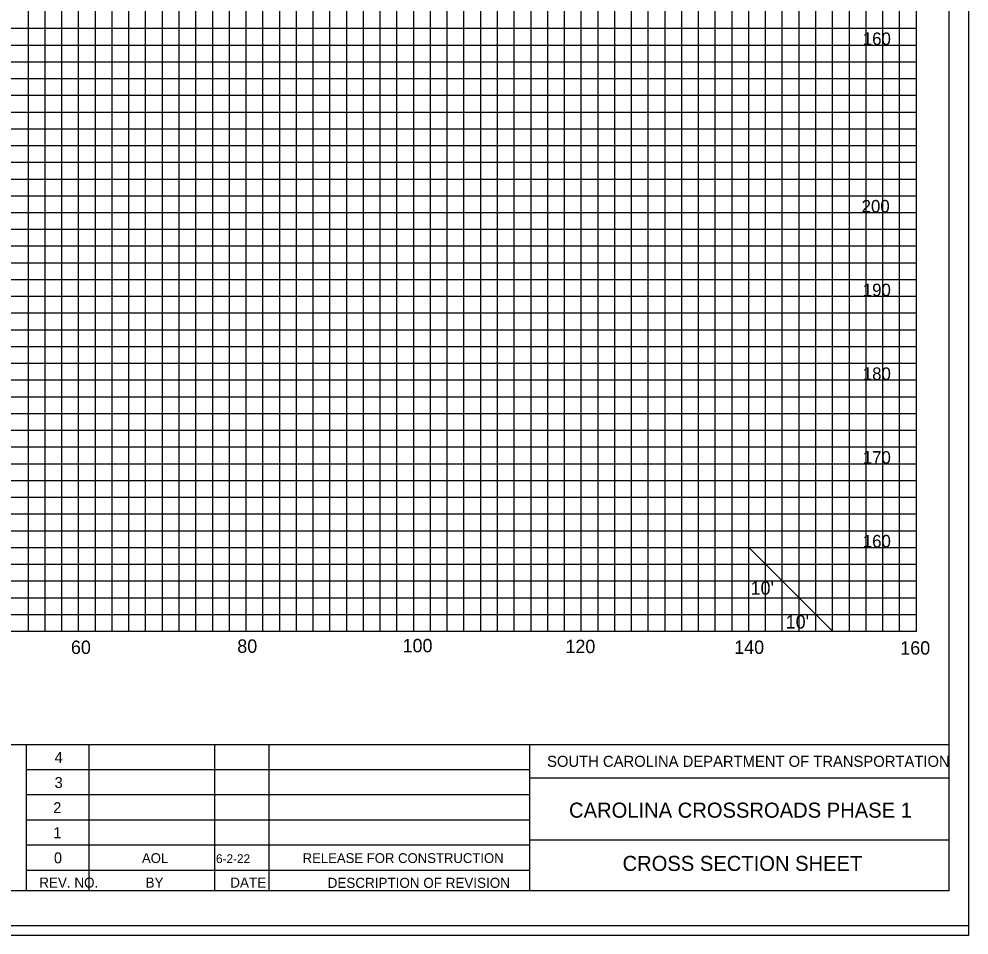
# Model space of a CAD drawing. Extents: x 967 to 1326, y 964 to 1184.
# Drawn here: x 1212.9 to 1326.3, y 963.7 to 1073.1 of the extents above; entities that cross this region are included whole.
import ezdxf

# ---------------------------------------------------------------- set-up
doc = ezdxf.new("R2010")
doc.units = 0
for name, color, linetype in [('Default', 7, 'Continuous'), ('RD_SHT_Bndy', 7, 'Continuous'), ('RD_SHT_IplotShp', 7, 'Continuous'), ('RD_SHT_Misc1', 7, 'Continuous'), ('RD_SHT_MjGrid', 7, 'Continuous'), ('RD_SHT_MnGrid', 7, 'Continuous'), ('RD_SHT_TX', 7, 'Continuous'), ('RD_Sketch1', 7, 'Continuous')]:
    doc.layers.add(name, color=color, linetype=linetype)

msp = doc.modelspace()

# ---------------------------------------------------------------- linework, layer by layer
at = {"layer": 'RD_SHT_Bndy'}
for p, q in [((1323.89, 1178.46), (1323.89, 968.98)), ((996.11, 986.49), (1323.89, 986.49)), ((1213.76, 968.94), (1213.76, 986.49)), ((1221.26, 968.95), (1221.26, 986.48)), ((1236.26, 968.95), (1236.26, 986.48)), ((1242.76, 968.95), (1242.76, 986.48)), ((1273.88, 968.98), (1273.88, 986.49)), ((1213.76, 983.48), (1273.88, 983.48)), ((1323.93, 982.43), (1273.88, 982.43)), ((1213.76, 980.48), (1273.88, 980.48)), ((1213.76, 977.48), (1273.88, 977.48)), ((1213.76, 974.48), (1273.88, 974.48)), ((1323.89, 975.04), (1273.88, 975.04)), ((1213.76, 971.48), (1273.88, 971.48)), ((1323.89, 968.98), (996.11, 968.98))]:
    msp.add_line(p, q, dxfattribs=at)
at = {"layer": 'RD_SHT_IplotShp'}
for points in [[(967.41, 963.72), (1326.28, 963.72), (1326.28, 1183.72), (967.41, 1183.72)], [(988.52, 964.84), (1326.28, 964.84), (1326.28, 1182.6), (988.52, 1182.6)]]:
    msp.add_lwpolyline(points, close=True, dxfattribs=at)
at = {"layer": 'RD_SHT_MjGrid'}
for p, q in [((1220, 1000), (1220, 1170)), ((1230, 1000), (1230, 1170)), ((1240, 1000), (1240, 1170)), ((1250, 1000), (1250, 1170)), ((1260, 1000), (1260, 1170)), ((1270, 1000), (1270, 1170)), ((1280, 1000), (1280, 1170)), ((1290, 1000), (1290, 1170)), ((1300, 1000), (1300, 1170)), ((1310, 1000), (1310, 1170)), ((1320, 1000), (1320, 1170)), ((1000, 1070), (1320, 1070)), ((1000, 1060), (1320, 1060)), ((1000, 1050), (1320, 1050)), ((1000, 1040), (1320, 1040)), ((1000, 1030), (1320, 1030)), ((1000, 1020), (1320, 1020)), ((1000, 1010), (1320, 1010)), ((1000, 1000), (1320, 1000))]:
    msp.add_line(p, q, dxfattribs=at)
at = {"layer": 'RD_SHT_MnGrid'}
for p, q in [((1214, 1000), (1214, 1170)), ((1216, 1000), (1216, 1170)), ((1218, 1000), (1218, 1170)), ((1222, 1000), (1222, 1170)), ((1224, 1000), (1224, 1170)), ((1226, 1000), (1226, 1170)), ((1228, 1000), (1228, 1170)), ((1232, 1000), (1232, 1170)), ((1234, 1000), (1234, 1170)), ((1236, 1000), (1236, 1170)), ((1238, 1000), (1238, 1170)), ((1242, 1000), (1242, 1170)), ((1244, 1000), (1244, 1170)), ((1246, 1000), (1246, 1170)), ((1248, 1000), (1248, 1170)), ((1252, 1000), (1252, 1170)), ((1254, 1000), (1254, 1170)), ((1256, 1000), (1256, 1170)), ((1258, 1000), (1258, 1170)), ((1262, 1000), (1262, 1170)), ((1264, 1000), (1264, 1170)), ((1266, 1000), (1266, 1170)), ((1268, 1000), (1268, 1170)), ((1272, 1000), (1272, 1170)), ((1274, 1000), (1274, 1170)), ((1276, 1000), (1276, 1170)), ((1278, 1000), (1278, 1170)), ((1282, 1000), (1282, 1170)), ((1284, 1000), (1284, 1170)), ((1286, 1000), (1286, 1170)), ((1288, 1000), (1288, 1170)), ((1292, 1000), (1292, 1170)), ((1294, 1000), (1294, 1170)), ((1296, 1000), (1296, 1170)), ((1298, 1000), (1298, 1170)), ((1302, 1000), (1302, 1170)), ((1304, 1000), (1304, 1170)), ((1306, 1000), (1306, 1170)), ((1308, 1000), (1308, 1170)), ((1312, 1000), (1312, 1170)), ((1314, 1000), (1314, 1170)), ((1316, 1000), (1316, 1170)), ((1318, 1000), (1318, 1170)), ((1000, 1072), (1320, 1072)), ((1000, 1068), (1320, 1068)), ((1000, 1066), (1320, 1066)), ((1000, 1064), (1320, 1064)), ((1000, 1062), (1320, 1062)), ((1000, 1058), (1320, 1058)), ((1000, 1056), (1320, 1056)), ((1000, 1054), (1320, 1054)), ((1000, 1052), (1320, 1052)), ((1000, 1048), (1320, 1048)), ((1000, 1046), (1320, 1046)), ((1000, 1044), (1320, 1044)), ((1000, 1042), (1320, 1042)), ((1000, 1038), (1320, 1038)), ((1000, 1036), (1320, 1036)), ((1000, 1034), (1320, 1034)), ((1000, 1032), (1320, 1032)), ((1000, 1028), (1320, 1028)), ((1000, 1026), (1320, 1026)), ((1000, 1024), (1320, 1024)), ((1000, 1022), (1320, 1022)), ((1000, 1018), (1320, 1018)), ((1000, 1016), (1320, 1016)), ((1000, 1014), (1320, 1014)), ((1000, 1012), (1320, 1012)), ((1000, 1008), (1320, 1008)), ((1000, 1006), (1320, 1006)), ((1000, 1004), (1320, 1004)), ((1000, 1002), (1320, 1002))]:
    msp.add_line(p, q, dxfattribs=at)
at = {"layer": 'RD_SHT_TX'}
msp.add_line((1300, 1010), (1310, 1000), dxfattribs=at)
at = {"layer": 'RD_Sketch1'}
msp.add_lwpolyline([(967.41, 963.72), (1326.28, 963.72), (1326.28, 1183.72), (967.41, 1183.72)], close=True, dxfattribs=at)

# ---------------------------------------------------------------- texts
at = {"layer": 'Default'}
for s, p in [('160', (1313.61, 1070)), ('200', (1313.47, 1050)), ('190', (1313.61, 1040)), ('180', (1313.61, 1030)), ('170', (1313.61, 1020)), ('160', (1313.61, 1010))]:
    msp.add_text(s, height=1.5, dxfattribs=at).set_placement(p)
at = {"layer": 'RD_SHT_Misc1'}
for s, height, p in [('AOL', 1.17, (1227.56, 972.32)), ('6-2-22', 1.053, (1236.4, 972.31)), ('RELEASE FOR CONSTRUCTION', 1.17, (1246.74, 972.32))]:
    msp.add_text(s, height=height, dxfattribs=at).set_placement(p)
at = {"layer": 'RD_SHT_TX'}
for s, height, p in [("10'", 1.6, (1300.21, 1004.36)), ("10'", 1.6, (1304.4, 1000.32)), ('100', 1.6, (1258.67, 997.48)), ('60', 1.6, (1219.08, 997.28)), ('80', 1.6, (1238.94, 997.42)), ('120', 1.6, (1278.11, 997.38)), ('140', 1.6, (1298.26, 997.29)), ('160', 1.6, (1318.08, 997.2)), ('4', 1.3, (1217.13, 984.28)), ('SOUTH CAROLINA DEPARTMENT OF TRANSPORTATION', 1.32, (1275.92, 983.8)), ('3', 1.3, (1217.13, 981.28)), ('2', 1.3, (1216.97, 978.28)), ('1', 1.3, (1216.97, 975.28)), ('0', 1.3, (1217.05, 972.28)), ('REV. NO.', 1.2, (1215.3, 969.38)), ('BY', 1.2, (1227.99, 969.38)), ('DATE', 1.2, (1238.1, 969.38)), ('DESCRIPTION OF REVISION', 1.2, (1249.73, 969.35))]:
    msp.add_text(s, height=height, dxfattribs=at).set_placement(p)
for s, p in [('CAROLINA CROSSROADS PHASE 1', (1278.54, 977.73)), ('CROSS SECTION SHEET', (1284.93, 971.37))]:
    msp.add_text(s, height=1.8, rotation=0, dxfattribs=at).set_placement(p)

doc.saveas('drawing.dxf')
